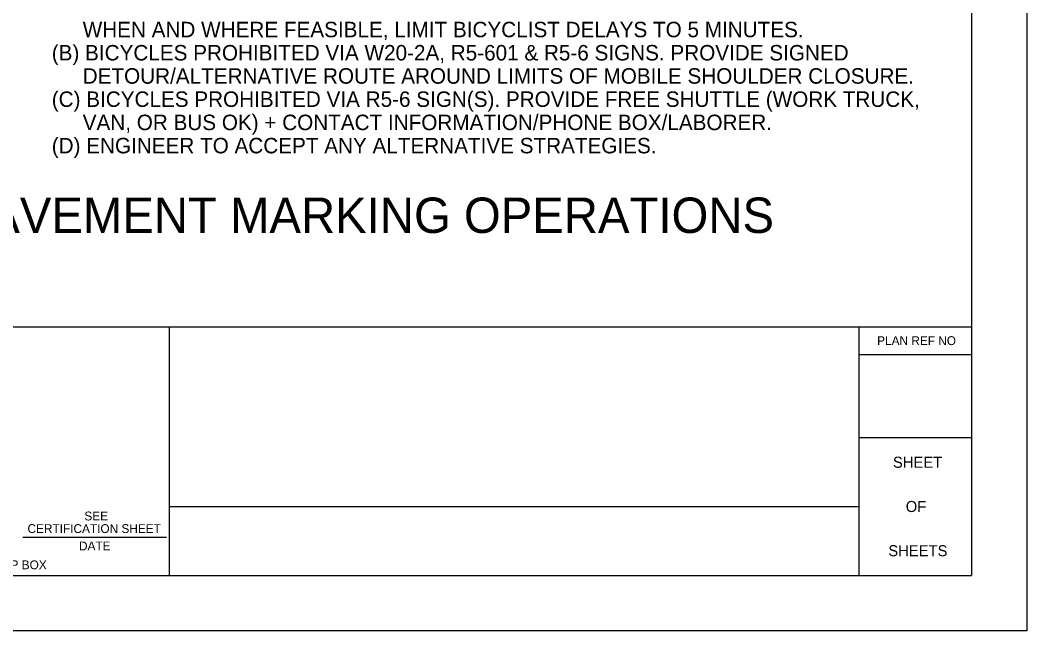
# Model space of a CAD drawing. Extents: x 0 to 17, y 0 to 11.
# Drawn here: x 12.446 to 17, y 0 to 2.762 of the extents above; entities that cross this region are included whole.
import ezdxf

# ---------------------------------------------------------------- set-up
doc = ezdxf.new("R2010")
doc.units = 0
for name, color, linetype in [('SH_GI_PlotLimits', 7, 'Continuous'), ('SH_GI_SheetBorder1', 7, 'Continuous'), ('SH_GI_SheetBorder2', 7, 'Continuous'), ('SH_GI_SheetBorder3', 7, 'Continuous'), ('SH_GI_SheetTextInCells', 7, 'Continuous'), ('TR_WZ_WorkZoneTextCurrent', 7, 'Continuous')]:
    doc.layers.add(name, color=color, linetype=linetype)

msp = doc.modelspace()

# ---------------------------------------------------------------- linework, layer by layer
at = {"layer": 'SH_GI_PlotLimits'}
msp.add_lwpolyline([(0, 11), (17, 11), (17, 0), (0, 0)], close=True, dxfattribs=at)
at = {"layer": 'SH_GI_SheetBorder1'}
msp.add_line((12.4584, 0.4233), (13.1083, 0.4233), dxfattribs=at)
at = {"layer": 'SH_GI_SheetBorder2'}
msp.add_line((13.12, 0.5625), (16.24, 0.5625), dxfattribs=at)
at = {"layer": 'SH_GI_SheetBorder3'}
for p, q in [((16.75, 10.75), (16.75, 0.25)), ((1, 1.375), (16.75, 1.375)), ((13.12, 1.3759), (13.12, 0.25)), ((16.24, 1.375), (16.24, 0.25)), ((16.24, 1.25), (16.75, 1.25)), ((16.24, 0.875), (16.75, 0.875)), ((1, 0.25), (16.75, 0.25))]:
    msp.add_line(p, q, dxfattribs=at)

# ---------------------------------------------------------------- texts
at = {"layer": 'SH_GI_SheetTextInCells'}
for s, height, p in [('PLAN REF NO', 0.04, (16.3228, 1.2925)), ('SHEET', 0.05, (16.394, 0.7375)), ('OF', 0.05, (16.4521, 0.5375)), ('SEE', 0.04, (12.7366, 0.4995)), ('CERTIFICATION SHEET', 0.04, (12.4793, 0.4425)), ('DATE', 0.04, (12.7123, 0.3641)), ('SHEETS', 0.05, (16.3733, 0.3375)), ('STAMP BOX', 0.04, (12.2541, 0.2786))]:
    msp.add_text(s, height=height, dxfattribs=at).set_placement(p)
at = {"layer": 'TR_WZ_WorkZoneTextCurrent'}
for s, height, p in [('WHEN AND WHERE FEASIBLE, LIMIT BICYCLIST DELAYS TO 5 MINUTES.', 0.07, (12.729, 2.6847)), ('(B) BICYCLES PROHIBITED VIA W20-2A, R5-601 & R5-6 SIGNS. PROVIDE SIGNED ', 0.07, (12.589, 2.5797)), ('DETOUR/ALTERNATIVE ROUTE AROUND LIMITS OF MOBILE SHOULDER CLOSURE.', 0.07, (12.729, 2.4747)), ('(C) BICYCLES PROHIBITED VIA R5-6 SIGN(S). PROVIDE FREE SHUTTLE (WORK TRUCK, ', 0.07, (12.589, 2.3697)), ('VAN, OR BUS OK) + CONTACT INFORMATION/PHONE BOX/LABORER.', 0.07, (12.729, 2.2647)), ('(D) ENGINEER TO ACCEPT ANY ALTERNATIVE STRATEGIES.', 0.07, (12.589, 2.1597)), ('FREEWAY (2+ LANES): MOBILE SINGLE RIGHT LANE CLOSURE FOR PAVEMENT MARKING OPERATIONS', 0.16, (5.1148, 1.7997))]:
    msp.add_text(s, height=height, rotation=360, dxfattribs=at).set_placement(p)

doc.saveas('drawing.dxf')
